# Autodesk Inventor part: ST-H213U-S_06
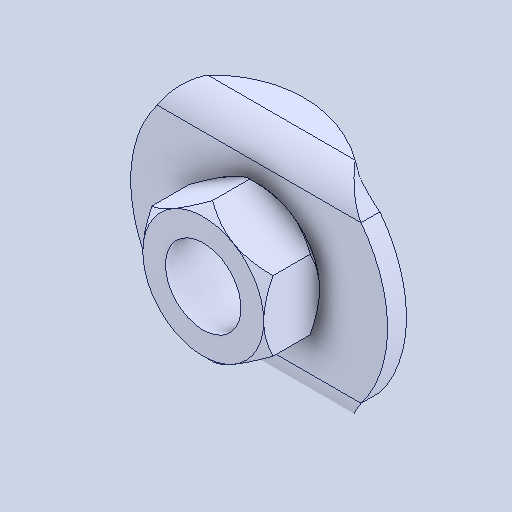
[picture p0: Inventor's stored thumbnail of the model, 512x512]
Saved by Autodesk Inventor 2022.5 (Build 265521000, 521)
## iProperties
Created: 2024-07
Part Number: ST-H213U-S_06
Material: 一般
Document SubType Name: Modeling
Designer: ImaoCorp
Density: 1 g/cm^3
Appearance: 既定
Author: ImaoCorp
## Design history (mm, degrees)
feature "ST-H213U-S_06"
node "ソリッド1"
